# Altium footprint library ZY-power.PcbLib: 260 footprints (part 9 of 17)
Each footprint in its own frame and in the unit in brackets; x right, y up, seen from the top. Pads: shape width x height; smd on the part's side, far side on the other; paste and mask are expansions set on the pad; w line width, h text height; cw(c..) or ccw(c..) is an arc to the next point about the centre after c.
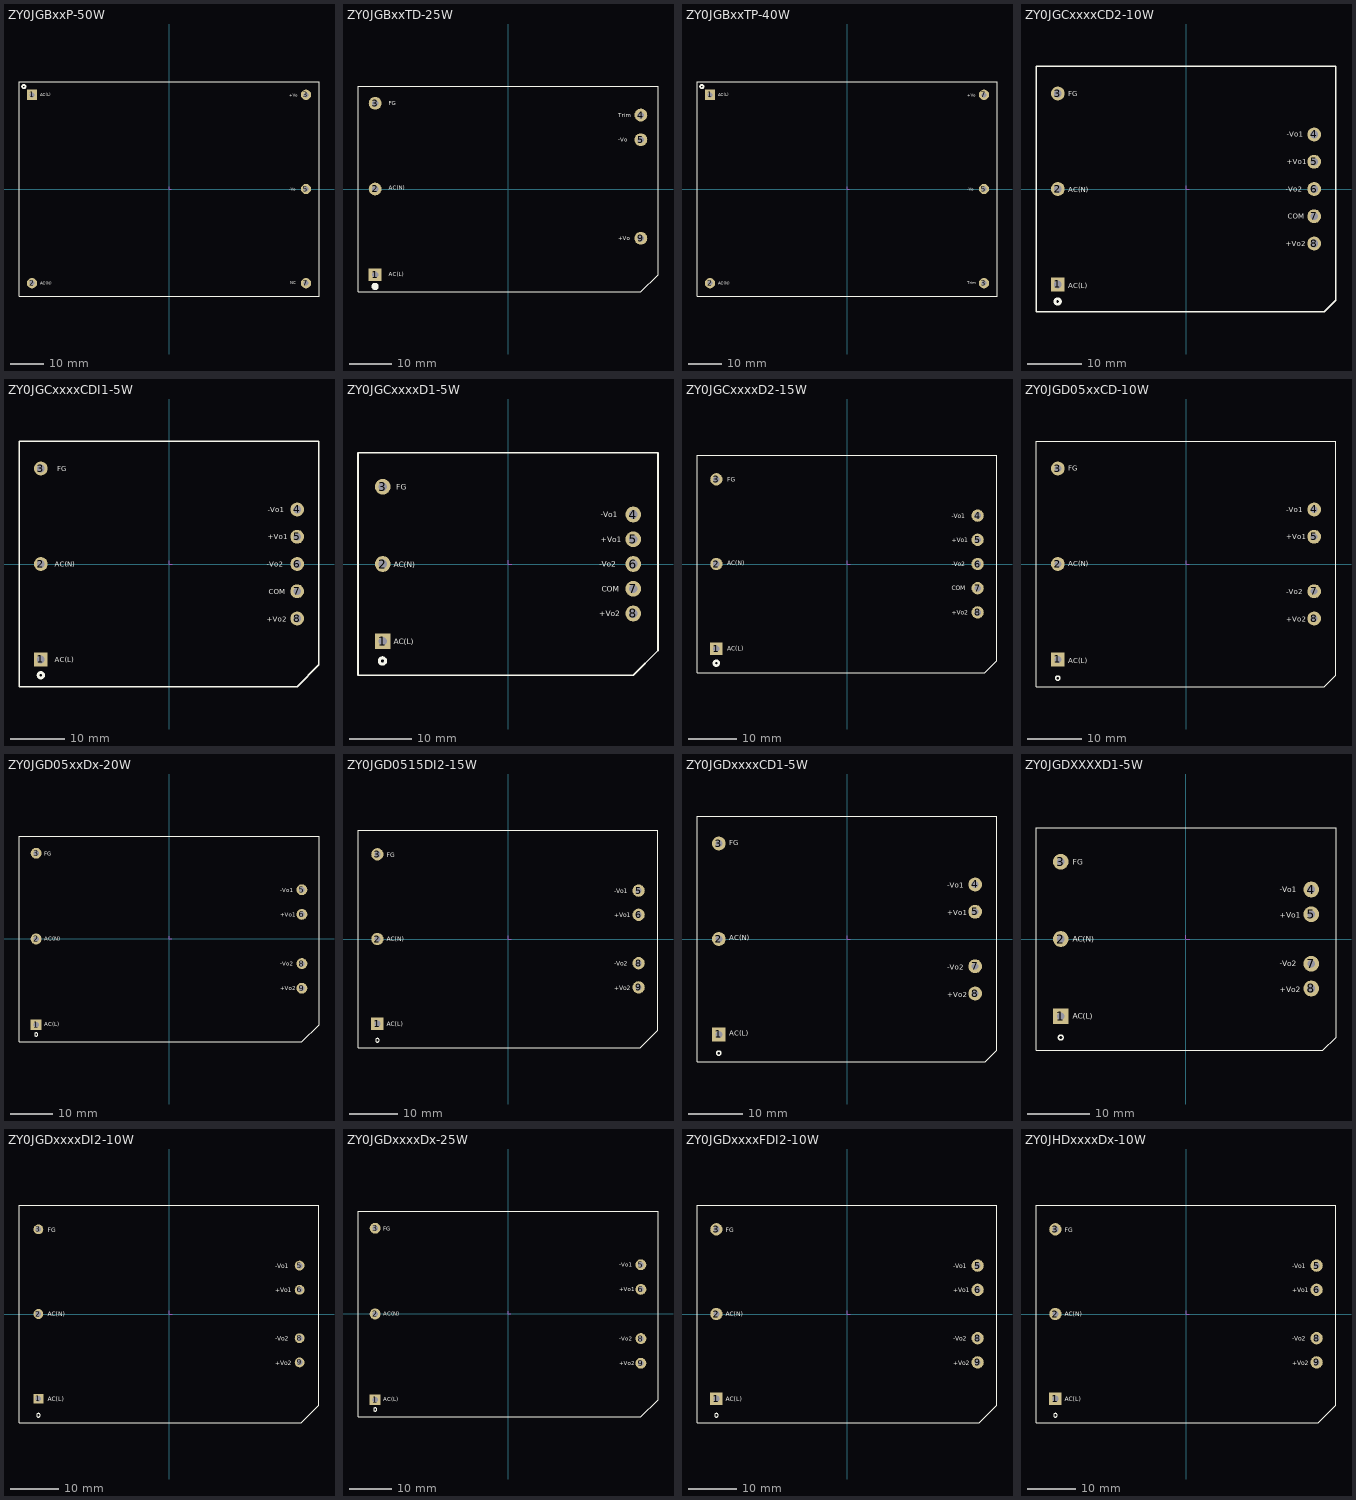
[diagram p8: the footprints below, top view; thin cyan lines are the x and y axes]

## ZY0JGBxxP-50W [mil]
height 984.25
pads (5):
  rect 120x120 hole 60: 1(-1600,1100)
  round 120 hole 60: 2(-1600,-1100) 3(1600,1100) 5(1600,0) 7(1600,-1100)
Top Overlay:
  circle w20: c-1696,1196 r20
  lines w10: -1751.97,-1250 1751.97,-1250 1751.97,1250 -1751.97,1250 -1751.97,-1250
  text "-Vo" at 1402,-19 h36
  text "AC(N)" at -1505,-1117 h36
  text "+Vo" at 1402,1079 h36
  text "AC(L)" at -1505,1083 h36
  text "NC" at 1416.66,-1114 h36
Mechanical 15:
  lines w5: 0,25 0,0 25,0

## ZY0JGBxxTD-25W [mm]
pads (6):
  rect 3x3 hole 1.5: 1(-31,-20)
  round 3 hole 1.5: 2(-31,0) 3(-31,20) 4(31,17.25) 5(31,11.5) 9(31,-11.5)
Top Overlay:
  circle w0.889: c-31.009,-22.733 r0.402
  lines w0.2: -35,-24 -35,24 35,24 35,-20 31,-24 -35,-24
  text "+Vo" at 25.781,-11.938 h0.91
  text "-Vo" at 25.781,11.049 h0.91
  text "Trim" at 25.772,16.764 h0.91
  text "FG" at -27.813,19.558 h0.91
  text "AC(N)" at -27.813,-0.229 h0.91
  text "AC(L)" at -27.813,-20.32 h0.91

## ZY0JGBxxTP-40W [mil]
height 984.25
pads (5):
  rect 120x120 hole 60: 1(-1600,1100)
  round 120 hole 60: 2(-1600,-1100) 3(1600,-1100) 5(1600,0) 7(1600,1100)
Top Overlay:
  circle w20: c-1696,1196 r20
  lines w10: -1751.97,-1250 -1751.97,1250 1751.97,1250 1751.97,-1250 -1751.97,-1250
  text "Trim" at 1401.66,-1112 h36
  text "AC(L)" at -1505,1083 h36
  text "+Vo" at 1402,1079 h36
  text "AC(N)" at -1505,-1117 h36
  text "-Vo" at 1402,-19 h36
Mechanical 15:
  lines w5: 0,25 0,0 25,0

## ZY0JGCxxxxCD2-10W [mm]
height 20.5
pads (8):
  rect 2.54x2.54 hole 1.397: 1(-23.5,-17.5)
  round 2.54 hole 1.397: 2(-23.5,0) 3(-23.5,17.5) 4(23.5,10) 5(23.5,5) 6(23.5,0) 7(23.5,-5) 8(23.5,-10)
Top Overlay:
  circle w0.508: c-23.52,-20.625 r0.508
  lines w0.254: -27.5,-22.5 25.379,-22.5 27.5,-20.379 27.5,22.5 -27.5,22.5 -27.5,-22.5
  text "+Vo2" at 18.295,-10.49 h0.91
  text "-Vo2" at 18.295,-0.47 h0.91
  text "-Vo1" at 18.491,9.55 h0.91
  text "COM" at 18.659,-5.48 h0.91
  text "+Vo1" at 18.491,4.54 h0.91
  text "FG" at -21.595,17.043 h0.91
  text "AC(N)" at -21.595,-0.572 h0.91
  text "AC(L)" at -21.595,-18.186 h0.91
Mechanical 15:
  lines w0.127: 0,0.635 0,0 0.635,0

## ZY0JGCxxxxCDI1-5W [mm]
height 20.5
pads (8):
  rect 2.54x2.54 hole 1.397: 1(-23.5,-17.5)
  round 2.54 hole 1.397: 2(-23.5,0) 3(-23.5,17.5) 4(23.5,10) 5(23.5,5) 6(23.5,0) 7(23.5,-5) 8(23.5,-10)
Top Overlay:
  circle w0.508: c-23.495,-20.396 r0.508
  lines w0.254: -27.5,-22.5 23.5,-22.5 27.5,-18.5 27.5,22.5 -27.5,22.5 -27.5,-22.5
  text "COM" at 18.303,-5.544 h0.91
  text "FG" at -20.523,17.018 h0.91
  text "AC(N)" at -20.955,-0.508 h0.91
  text "-Vo1" at 18.136,9.525 h0.91
  text "+Vo1" at 18.136,4.502 h0.91
  text "AC(L)" at -20.955,-17.983 h0.91
  text "-Vo2" at 17.94,-0.521 h0.91
  text "+Vo2" at 17.94,-10.566 h0.91
Mechanical 15:
  lines w0.127: 0,0.635 0,0 0.635,0

## ZY0JGCxxxxD1-5W [mm]
height 20.5
pads (8):
  rect 2.54x2.54 hole 1.397: 1(-20.25,-12.5)
  round 2.54 hole 1.397: 2(-20.25,0) 3(-20.25,12.5) 4(20.25,8) 5(20.25,4) 6(20.25,0) 7(20.25,-4) 8(20.25,-8)
Top Overlay:
  circle w0.508: c-20.295,-15.672 r0.508
  lines w0.254: -24.25,-18 -24.25,18 24.25,18 24.25,-14 20.25,-18 -24.25,-18
  text "AC(L)" at -18.466,-12.954 h0.91
  text "+Vo1" at 14.961,3.518 h0.91
  text "-Vo1" at 14.961,7.518 h0.91
  text "AC(N)" at -18.466,-0.533 h0.91
  text "FG" at -18.059,12.014 h0.91
  text "COM" at 15.128,-4.483 h0.91
  text "-Vo2" at 14.765,-0.483 h0.91
  text "+Vo2" at 14.765,-8.484 h0.91
Mechanical 15:
  lines w0.127: 0,0.635 0,0 0.635,0

## ZY0JGCxxxxD2-15W [mm]
height 22.5
pads (8):
  rect 2.54x2.54 hole 1.397: 1(-27,-17.5)
  round 2.54 hole 1.397: 2(-27,0) 3(-27,17.5) 4(27,10) 5(27,5) 6(27,0) 7(27,-5) 8(27,-10)
Top Overlay:
  circle w0.508: c-27,-20.498 r0.508
  lines w0.254: -31,-22.5 28.503,-22.5 31,-20.003 31,22.5 -31,22.5 -31,-22.5
  text "-Vo1" at 21.676,9.5 h0.91
  text "+Vo2" at 21.676,-10.439 h0.91
  text "FG" at -24.719,17.043 h0.91
  text "AC(N)" at -24.719,-0.267 h0.91
  text "AC(L)" at -24.719,-17.882 h0.91
  text "+Vo1" at 21.676,4.516 h0.91
  text "-Vo2" at 21.676,-0.469 h0.91
  text "COM" at 21.676,-5.454 h0.91
Mechanical 15:
  lines w0.127: 0,0.635 0,0 0.635,0

## ZY0JGD05xxCD-10W [mm]
pads (7):
  rect 2.54x2.54 hole 1.27: 1(-23.5,-17.5)
  round 2.54 hole 1.27: 2(-23.5,0) 3(-23.5,17.5) 4(23.5,10) 5(23.5,5) 7(23.5,-5) 8(23.5,-10)
Top Overlay:
  circle w0.254: c-23.5,-20.929 r0.381
  lines w0.127: -27.5,-22.5 -27.5,22.5 27.5,22.5 27.5,-20.379 25.379,-22.5 -27.5,-22.5
  text "-Vo2" at 18.42,-5.5 h0.91
  text "+Vo1" at 18.42,4.5 h0.91
  text "AC(L)" at -21.59,-18.161 h0.91
  text "AC(N)" at -21.595,-0.457 h0.91
  text "FG" at -21.595,17.069 h0.91
  text "+Vo2" at 18.42,-10.566 h0.91
  text "-Vo1" at 18.42,9.5 h0.91
Mechanical 15:
  lines w0.127: 0,0.635 0,0 0.635,0

## ZY0JGD05xxDx-20W [mm]
pads (7):
  rect 2.54x2.54 hole 1.27: 1(-31,-20)
  round 2.54 hole 1.27: 2(-31,0) 3(-31,20) 5(31,11.5) 6(31,5.75) 8(31,-5.75) 9(31,-11.5)
Top Overlay:
  circle w0.254: c-31,-22.286 r0.381
  lines w0.254: -35,-24.003 30.988,-24.003 35,-19.991 35,24 -35,24 -35,-24.003
  text "FG" at -29.095,19.431 h0.91
  text "AC(N)" at -29.095,-0.356 h0.91
  text "AC(L)" at -29.095,-20.356 h0.91
  text "+Vo2" at 25.92,-11.938 h0.91
  text "-Vo2" at 25.92,-6.223 h0.91
  text "-Vo1" at 25.92,10.922 h0.91
  text "+Vo1" at 25.92,5.207 h0.91
Mechanical 15:
  lines w0.127: 0,0.635 0,0 0.635,0

## ZY0JGD0515DI2-15W [mm]
pads (7):
  rect 2.54x2.54 hole 1.27: 1(-27,-17.5)
  round 2.54 hole 1.27: 2(-27,0) 3(-27,17.5) 5(27,10) 6(27,5) 8(27,-5) 9(27,-10)
Top Overlay:
  circle w0.254: c-27,-20.929 r0.381
  lines w0.254: -31,-22.5 -31,22.5 31,22.5 31,-18.825 27.325,-22.5 -31,-22.5
  text "FG" at -25.095,16.942 h0.91
  text "AC(N)" at -25.095,-0.457 h0.91
  text "AC(L)" at -25.095,-18.034 h0.91
  text "-Vo2" at 21.92,-5.5 h0.91
  text "+Vo1" at 21.92,4.5 h0.91
  text "+Vo2" at 21.92,-10.566 h0.91
  text "-Vo1" at 21.92,9.5 h0.91
Mechanical 15:
  lines w0.127: 0,0.635 0,0 0.635,0

## ZY0JGDxxxxCD1-5W [mm]
pads (7):
  rect 2.54x2.54 hole 1.27: 1(-23.5,-17.5)
  round 2.54 hole 1.27: 2(-23.5,0) 3(-23.5,17.5) 4(23.5,10) 5(23.5,5) 7(23.5,-5) 8(23.5,-10)
Top Overlay:
  circle w0.254: c-23.5,-20.929 r0.381
  lines w0.127: -27.5,-22.5 -27.5,22.5 27.5,22.5 27.5,-20.379 25.379,-22.5 -27.5,-22.5
  text "-Vo2" at 18.42,-5.627 h0.91
  text "+Vo1" at 18.42,4.373 h0.91
  text "AC(L)" at -21.595,-17.729 h0.91
  text "AC(N)" at -21.595,-0.203 h0.91
  text "FG" at -21.595,17.196 h0.91
  text "+Vo2" at 18.42,-10.693 h0.91
  text "-Vo1" at 18.42,9.373 h0.91
Mechanical 15:
  lines w0.127: 0,0.635 0,0 0.635,0

## ZY0JGDXXXXD1-5W [mm]
pads (7):
  rect 2.54x2.54 hole 1.27: 1(-20.25,-12.5)
  round 2.54 hole 1.27: 2(-20.25,0) 3(-20.25,12.5) 4(20.25,8) 5(20.25,4) 7(20.25,-4) 8(20.25,-8)
Top Overlay:
  circle w0.254: c-20.25,-15.929 r0.381
  lines w0.127: -24.25,-18 22.129,-18 24.25,-15.879 24.25,18 -24.25,18 -24.25,-18
  text "-Vo1" at 15.17,7.544 h0.91
  text "+Vo2" at 15.17,-8.585 h0.91
  text "FG" at -18.345,11.963 h0.91
  text "AC(N)" at -18.345,-0.432 h0.91
  text "AC(L)" at -18.345,-12.878 h0.91
  text "+Vo1" at 15.17,3.429 h0.91
  text "-Vo2" at 15.17,-4.445 h0.91
Mechanical 15:
  lines w0.127: 0,0.635 0,0 0.635,0

## ZY0JGDxxxxDI2-10W [mil]
pads (7):
  rect 80x80 hole 45: 1(-1062.99,-688.98)
  round 80 hole 45: 2(-1062.99,0) 3(-1062.99,688.98) 5(1062.99,393.7) 6(1062.99,196.85) 8(1062.99,-196.85) 9(1062.99,-393.7)
Top Overlay:
  circle w10: c-1062.99,-823.98 r15
  lines w10: -1220.47,-885.83 1075.79,-885.83 1220.47,-741.14 1220.47,885.83 -1220.47,885.83 -1220.47,-885.83
  text "-Vo1" at 862.99,374 h36
  text "+Vo2" at 862.99,-416 h36
  text "+Vo1" at 862.99,177.15 h36
  text "-Vo2" at 862.99,-216.55 h36
  text "AC(L)" at -987.99,-710 h36
  text "AC(N)" at -987.99,-18 h36
  text "FG" at -987.99,667 h36
Mechanical 15:
  lines w5: 0,25 0,0 25,0

## ZY0JGDxxxxDx-25W [mm]
pads (7):
  rect 2.54x2.54 hole 1.27: 1(-31,-20)
  round 2.54 hole 1.27: 2(-31,0) 3(-31,20) 5(31,11.5) 6(31,5.75) 8(31,-5.75) 9(31,-11.5)
Top Overlay:
  circle w0.254: c-31,-22.286 r0.381
  lines w0.254: -35,-24.003 -35,24 35,24 35,-19.991 30.988,-24.003 -35,-24.003
  text "+Vo1" at 25.92,5.334 h0.91
  text "-Vo1" at 25.92,11.049 h0.91
  text "-Vo2" at 25.92,-6.223 h0.91
  text "+Vo2" at 25.92,-11.938 h0.91
  text "AC(L)" at -29.095,-20.356 h0.91
  text "AC(N)" at -29.095,-0.356 h0.91
  text "FG" at -29.095,19.431 h0.91
Mechanical 15:
  lines w0.127: 0,0.635 0,0 0.635,0

## ZY0JGDxxxxFDI2-10W [mm]
pads (7):
  rect 2.54x2.54 hole 1.27: 1(-27,-17.5)
  round 2.54 hole 1.27: 2(-27,0) 3(-27,17.5) 5(27,10) 6(27,5) 8(27,-5) 9(27,-10)
Top Overlay:
  circle w0.254: c-27,-20.929 r0.381
  lines w0.254: -31,-22.5 27.325,-22.5 31,-18.825 31,22.5 -31,22.5 -31,-22.5
  text "-Vo1" at 21.92,9.5 h0.91
  text "+Vo2" at 21.92,-10.566 h0.91
  text "+Vo1" at 21.92,4.5 h0.91
  text "-Vo2" at 21.92,-5.5 h0.91
  text "AC(L)" at -25.095,-18.034 h0.91
  text "AC(N)" at -25.095,-0.457 h0.91
  text "FG" at -25.095,16.942 h0.91
Mechanical 15:
  lines w0.127: 0,0.635 0,0 0.635,0

## ZY0JHDxxxxDx-10W [mm]
pads (7):
  rect 2.54x2.54 hole 1.27: 1(-27,-17.5)
  round 2.54 hole 1.27: 2(-27,0) 3(-27,17.5) 5(27,10) 6(27,5) 8(27,-5) 9(27,-10)
Top Overlay:
  circle w0.254: c-27,-20.929 r0.381
  lines w0.254: -31,-22.5 -31,22.5 31,22.5 31,-18.825 27.325,-22.5 -31,-22.5
  text "FG" at -25.095,16.942 h0.91
  text "AC(N)" at -25.095,-0.457 h0.91
  text "AC(L)" at -25.095,-18.034 h0.91
  text "-Vo2" at 21.92,-5.5 h0.91
  text "+Vo1" at 21.92,4.5 h0.91
  text "+Vo2" at 21.92,-10.566 h0.91
  text "-Vo1" at 21.92,9.5 h0.91
Mechanical 15:
  lines w0.127: 0,0.635 0,0 0.635,0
